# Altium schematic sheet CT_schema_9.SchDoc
size 274 x 160 mm
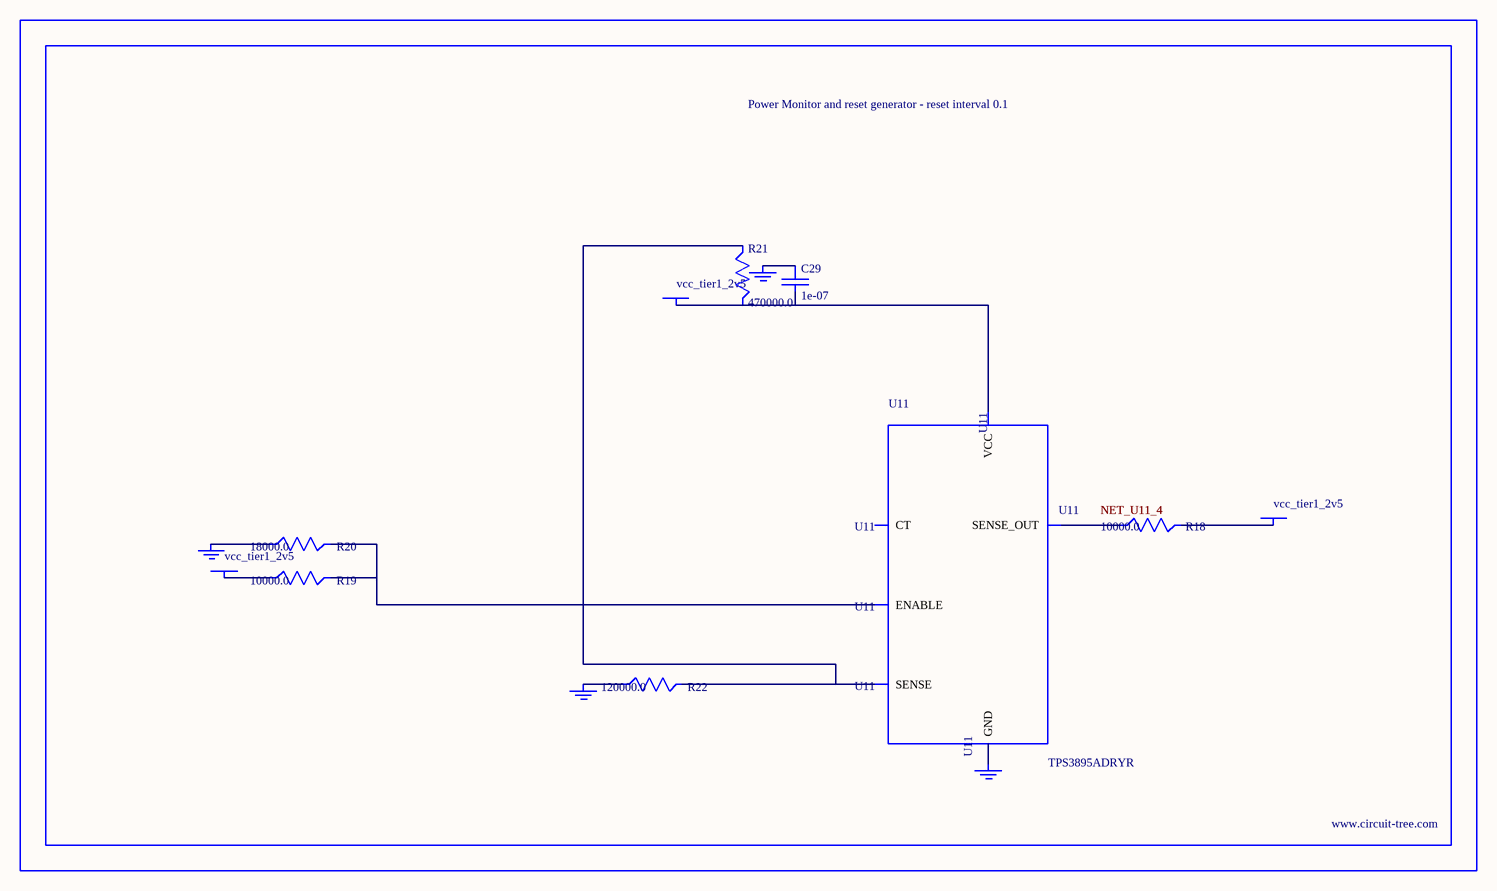
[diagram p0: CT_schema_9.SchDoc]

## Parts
BORDER8  (no value)
C29  1e-07  [C0402]
GND_INSTANCE_8_0  (no value)
GND_INSTANCE_8_1  (no value)
GND_INSTANCE_8_2  (no value)
GND_INSTANCE_8_3  (no value)
POWER_INSTANCE_8_0  vcc_tier1_2v5
POWER_INSTANCE_8_1  vcc_tier1_2v5
POWER_INSTANCE_8_2  vcc_tier1_2v5
R18  10000.0  [R0603]
R19  10000.0  [R0603]
R20  18000.0  [R0603]
R21  470000.0  [R0603]
R22  120000.0  [R0603]
U11  TPS3895ADRYR  [SON-6]

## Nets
NetC29_1: C29.1 GND_INSTANCE_8_2.0(GND)
NetC29_2: C29.2 POWER_INSTANCE_8_2.0(PWR) R21.2 U11.6(VCC)
NetGND_INSTANCE_8_0_0: GND_INSTANCE_8_0.0(GND) R20.1
NetGND_INSTANCE_8_1_0: GND_INSTANCE_8_1.0(GND) R22.1
NetGND_INSTANCE_8_3_0: GND_INSTANCE_8_3.0(GND) U11.2(GND)
NetPOWER_INSTANCE_8_0_0: POWER_INSTANCE_8_0.0(PWR) R19.1
NetPOWER_INSTANCE_8_1_0: POWER_INSTANCE_8_1.0(PWR) R18.2
NetR18_1: R18.1 U11.4(SENSE_OUT)
NetR19_2: R19.2 R20.2 U11.1(ENABLE)
NetR21_1: R21.1 R22.2 U11.3(SENSE)

Not connected (* = marked no-connect by the designer): U11 5(CT)

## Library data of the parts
BORDER8 = BORDER_PAGE8
C29 = C0402C104K3RACTU
GND_INSTANCE_8_0-GND_INSTANCE_8_3 = GND
POWER_INSTANCE_8_0-POWER_INSTANCE_8_2 = PWR
R18 R19 = RC0603JR-0710KL
R20 = RC0603JR-0718KL
R21 = RC0603JR-07470KL
R22 = RC0603JR-07120KL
